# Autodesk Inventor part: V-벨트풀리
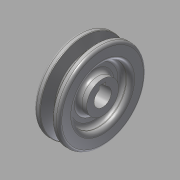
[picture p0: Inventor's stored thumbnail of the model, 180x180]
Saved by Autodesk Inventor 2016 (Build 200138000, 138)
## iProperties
Created: 2015-12
Part Number: V-벨트풀리
Material: 강철, 연강
Document SubType Name: Modeling
Designer: mduedu
Density: 7.86 g/cm^3
Appearance: 강철
Author: mduedu
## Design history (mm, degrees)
sketch "스케치1"
  geometry: L1 (-9.5, 0)-(9.5, 0); L2 (-9.5, 0)-(-9.5, 32.7); L3 (-9.5, 32.7)-(-4.825, 32.7); L4 (-4.825, 32.7)-(-2.074, 23.7); L5 (-2.074, 23.7)-(0, 23.7); L6 (0, 0)-(0, 23.7); L7 (9.5, 0)-(9.5, 32.7); L8 (9.5, 32.7)-(4.825, 32.7); L9 (4.825, 32.7)-(2.074, 23.7); L10 (2.074, 23.7)-(0, 23.7); L11 (-4, 30)-(4, 30); 3 further points
  constraints: 22 end point, 3 coincident, 3 perpendicular, 3 symmetric about line, 2 parallel, 2 point on line, 1 horizontal, 1 midpoint, 1 vertical alignment
  dimensions: "d0" = 19 distance between parallel lines of L7 L2; "d2" = 6.3 distance between parallel lines of L10 L11; "d3" = 34 deg angle of L9 L4; "d4" = 2.7 distance between parallel lines of L11 L8; "d5" = 60 diameter of L11 L1; "d6" = 8 distance of L11.end L11.start
revolve "회전1" sketch "스케치1" stored, may be unused: angle "d7" = 90 deg
sketch "스케치2"
  geometry: C1 r 21 at (0, 0); C2 r 12 at (0, 0); 1 further point
  constraints: 2 centre point, 2 coincident
  dimensions: "d8" = 42 diameter of C1; "d10" = 24 diameter of C2
extrude "돌출1" cut sketch "스케치2" distance "d11" = 6.5; taper "d12" = 0 deg
fillet "모깎기1" dims "d13" = 1, "d14" = 0.5, "d15" = 2
fillet "모깎기2" dims "d16" = 3
fillet "모깎기3" dims "d17" = 3
hole "구멍1" diameter "d20" = 13; stored, may be unused: countersink angle "d24" = 90 deg, drill point angle "d26" = 118 deg; dims "d18" = 10, "d19" = 10, "d21" = 6, "d22" = 4, "d23" = 2, "d25" = 8
sketch "스케치3"
  geometry: L1 (-2.5, 0)-(2.5, 0); L2 (2.5, 0)-(2.5, 8.8); L3 (2.5, 8.8)-(-2.5, 8.8); L4 (-2.5, 8.8)-(-2.5, 0); 2 further points
  constraints: 8 end point, 2 parallel, 1 coincident, 1 horizontal, 1 midpoint, 1 perpendicular
  dimensions: "d27" = 8.8 distance of L1.end L2.end; "d29" = 5 distance of L2.end L3.end
extrude "돌출2" cut sketch "스케치3" stored distance "d30" = 6.5; taper "d31" = 0 deg
node "솔리드1"
mirror "대칭1"
